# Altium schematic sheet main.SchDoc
size A4; SheetNumber: 2; SheetTotal: 5; SPICEModelCacheQOCYWOGJ: <root> / <DocumentId>QOCYWOGJ</DocumentId> / </root>
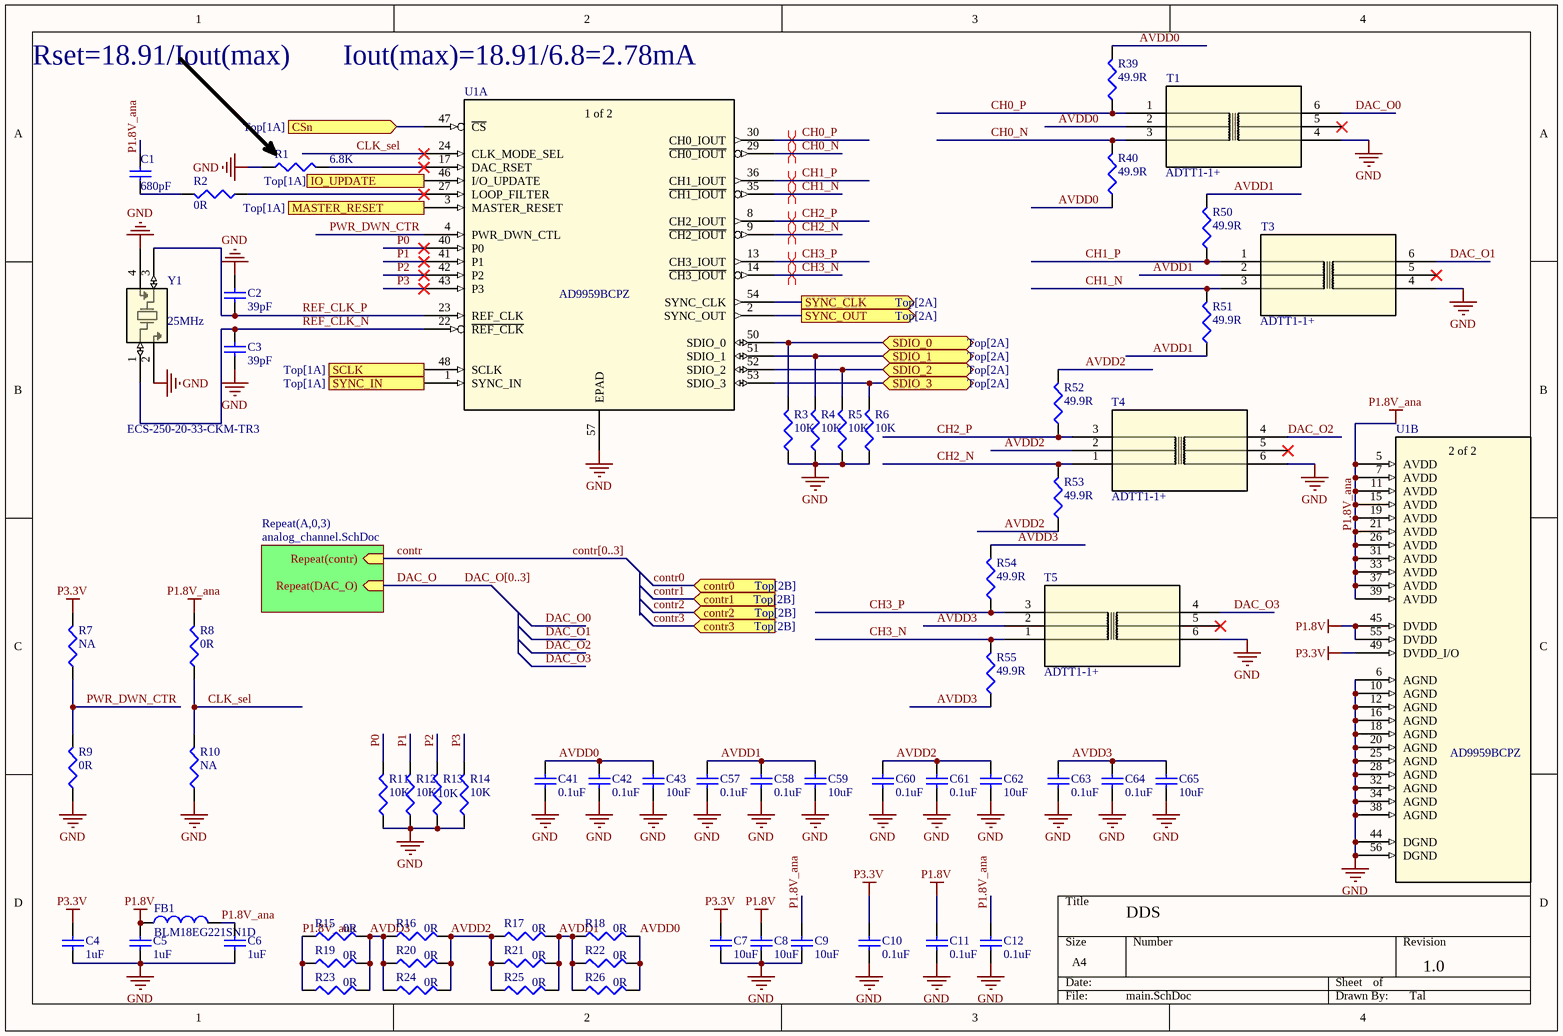
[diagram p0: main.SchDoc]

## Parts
C1  Capacitance: 680pF  [C0402]  (hidden comment: 680pF 50V)
C2  Capacitance: 39pF  [C0402]  (hidden comment: 39pF 50V)
C3  Capacitance: 39pF  [C0402]  (hidden comment: 39pF 50V)
C4  Capacitance: 1uF  [C0402]  (hidden comment: 1uF 25V)
C5  Capacitance: 1uF  [C0402]  (hidden comment: 1uF 25V)
C6  Capacitance: 1uF  [C0402]  (hidden comment: 1uF 25V)
C7  Capacitance: 10uF  [C0402]  (hidden comment: 10uF 10V)
C8  Capacitance: 10uF  [C0402]  (hidden comment: 10uF 10V)
C9  Capacitance: 10uF  [C0402]  (hidden comment: 10uF 10V)
C10  Capacitance: 0.1uF  [C0402]  (hidden comment: 0.1uF 50V)
C11  Capacitance: 0.1uF  [C0402]  (hidden comment: 0.1uF 50V)
C12  Capacitance: 0.1uF  [C0402]  (hidden comment: 0.1uF 50V)
C41  Capacitance: 0.1uF  [C0402]  (hidden comment: 0.1uF 50V)
C42  Capacitance: 0.1uF  [C0402]  (hidden comment: 0.1uF 50V)
C43  Capacitance: 10uF  [C0402]  (hidden comment: 10uF 10V)
C57  Capacitance: 0.1uF  [C0402]  (hidden comment: 0.1uF 50V)
C58  Capacitance: 0.1uF  [C0402]  (hidden comment: 0.1uF 50V)
C59  Capacitance: 10uF  [C0402]  (hidden comment: 10uF 10V)
C60  Capacitance: 0.1uF  [C0402]  (hidden comment: 0.1uF 50V)
C61  Capacitance: 0.1uF  [C0402]  (hidden comment: 0.1uF 50V)
C62  Capacitance: 10uF  [C0402]  (hidden comment: 10uF 10V)
C63  Capacitance: 0.1uF  [C0402]  (hidden comment: 0.1uF 50V)
C64  Capacitance: 0.1uF  [C0402]  (hidden comment: 0.1uF 50V)
C65  Capacitance: 10uF  [C0402]  (hidden comment: 10uF 10V)
FB1  BLM18EG221SN1D  [fb0603]
R1  6.8K  [R0402]
R2  0R  [R0402]
R3  10K  [R0402]
R4  10K  [R0402]
R5  10K  [R0402]
R6  10K  [R0402]
R7  NA  [R0402]
R8  0R  [R0402]
R9  0R  [R0402]
R10  NA  [R0402]
R11  10K  [R0402]
R12  10K  [R0402]
R13  10K  [R0402]
R14  10K  [R0402]
R15  0R  [R0805]
R16  0R  [R0805]
R17  0R  [R0805]
R18  0R  [R0805]
R19  0R  [R0805]
R20  0R  [R0805]
R21  0R  [R0805]
R22  0R  [R0805]
R23  0R  [R0805]
R24  0R  [R0805]
R25  0R  [R0805]
R26  0R  [R0805]
R39  49.9R  [R0402]
R40  49.9R  [R0402]
R50  49.9R  [R0402]
R51  49.9R  [R0402]
R52  49.9R  [R0402]
R53  49.9R  [R0402]
R54  49.9R  [R0402]
R55  49.9R  [R0402]
T1  ADTT1-1+  [CD542_MNC]
T3  ADTT1-1+  [CD542_MNC]
T4  ADTT1-1+  [CD542_MNC]
T5  ADTT1-1+  [CD542_MNC]
U1  AD9959BCPZ  [CP_56_1_ADI]  (parts A,B of 2)
Y1  ECS-250-20-33-CKM-TR3  [SMD4_ECX-32_3p2x2p5_ECS]

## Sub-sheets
Repeat(A,0,3) = analog_channel.SchDoc: Repeat(contr) (in), Repeat(DAC_O) (in)

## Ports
contr0 (in, see Top[2B]), contr1 (in, see Top[2B]), contr2 (in, see Top[2B]), contr3 (in, see Top[2B]), CSn (in, see Top[1A]), IO_UPDATE (in, see Top[1A]), MASTER_RESET (in, see Top[1A]), SCLK (in, see Top[1A]), SDIO_0 (bidir, see Top[2A]), SDIO_1 (bidir, see Top[2A]), SDIO_2 (bidir, see Top[2A]), SDIO_3 (bidir, see Top[2A]), SYNC_CLK (out, see Top[2A]), SYNC_IN (in, see Top[1A]), SYNC_OUT (out, see Top[2A])

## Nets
GND: C2.2 C3.1 C4.1 C5.1 C6.1 C7.1 C8.1 C9.1 C10.1 C11.1 C12.1 C41.1 C42.1 C43.1 C57.1 C58.1 C59.1 C60.1 C61.1 C62.1 C63.1 C64.1 C65.1 R1.1 R3.1 R4.1 R5.1 R6.1 R9.1 R10.1 R11.1 R12.1 R13.1 R14.1 T1.4 T3.4 T4.6 T5.6 U1.6(AGND) U1.10(AGND) U1.12(AGND) U1.16(AGND) U1.18(AGND) U1.20(AGND) U1.25(AGND) U1.28(AGND) U1.32(AGND) U1.34(AGND) U1.38(AGND) U1.44(DGND) U1.56(DGND) U1.57(EPAD) Y1.2 Y1.4
P1.8V: C5.2 C8.2 C11.2 FB1.1 U1.45(DVDD) U1.55(DVDD)
P1.8V_ana: C1.1 C6.2 C9.2 C12.2 FB1.2 R8.2 R15.1 R19.1 R23.1 U1.5(AVDD) U1.7(AVDD) U1.11(AVDD) U1.15(AVDD) U1.19(AVDD) U1.21(AVDD) U1.26(AVDD) U1.31(AVDD) U1.33(AVDD) U1.37(AVDD) U1.39(AVDD)
P3.3V: C4.2 C7.2 C10.2 R7.2 U1.49(DVDD_I/O)
AVDD0: C41.2 C42.2 C43.2 R18.2 R22.2 R26.2 R39.2 R40.1 T1.2
AVDD1: C57.2 C58.2 C59.2 R17.2 R18.1 R21.2 R22.1 R25.2 R26.1 R50.2 R51.1 T3.2
AVDD2: C60.2 C61.2 C62.2 R16.2 R17.1 R20.2 R21.1 R24.2 R25.1 R52.2 R53.1 T4.2
AVDD3: C63.2 C64.2 C65.2 R15.2 R16.1 R19.2 R20.1 R23.2 R24.1 R54.2 R55.1 T5.2
CH0_N: R40.2 T1.3 U1.29(~{CH0_IOUT})
CH0_P: R39.1 T1.1 U1.30(CH0_IOUT)
CH1_N: R51.2 T3.3 U1.35(~{CH1_IOUT})
CH1_P: R50.1 T3.1 U1.36(CH1_IOUT)
CH2_N: R53.2 T4.1 U1.9(~{CH2_IOUT})
CH2_P: R52.1 T4.3 U1.8(CH2_IOUT)
CH3_N: R55.2 T5.1 U1.14(~{CH3_IOUT})
CH3_P: R54.1 T5.3 U1.13(CH3_IOUT)
CLK_sel: R8.1 R10.2 U1.24(CLK_MODE_SEL)
CSn: U1.47(~{CS}) ; port CSn
DAC_O0: T1.6
DAC_O1: T3.6
DAC_O2: T4.4
DAC_O3: T5.4
IO_UPDATE: U1.46(I/O_UPDATE) ; port IO_UPDATE
MASTER_RESET: U1.3(MASTER_RESET) ; port MASTER_RESET
P0: R11.2 U1.40(P0)
P1: R12.2 U1.41(P1)
P2: R13.2 U1.42(P2)
P3: R14.2 U1.43(P3)
PWR_DWN_CTR: R7.1 R9.2 U1.4(PWR_DWN_CTL)
REF_CLK_N: C3.2 U1.22(~{REF_CLK}) Y1.1
REF_CLK_P: C2.1 U1.23(REF_CLK) Y1.3
SCLK: U1.48(SCLK) ; port SCLK
SDIO_0: R3.2 U1.50(SDIO_0) ; port SDIO_0
SDIO_1: R4.2 U1.51(SDIO_1) ; port SDIO_1
SDIO_2: R5.2 U1.52(SDIO_2) ; port SDIO_2
SDIO_3: R6.2 U1.53(SDIO_3) ; port SDIO_3
SYNC_CLK: U1.54(SYNC_CLK) ; port SYNC_CLK
SYNC_IN: U1.1(SYNC_IN) ; port SYNC_IN
SYNC_OUT: U1.2(SYNC_OUT) ; port SYNC_OUT
NetC1_2: C1.2 R2.2
NetR1_2: R1.2 U1.17(DAC_RSET)
NetR2_1: R2.1 U1.27(LOOP_FILTER)

Not connected (* = marked no-connect by the designer): T1 5*; T3 5*; T4 5*; T5 5*

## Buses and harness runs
bus contr[0..3]
bus DAC_O[0..3]

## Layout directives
differential pair: CH0_N, CH0_P, CH1_N, CH1_P, CH2_N, CH2_P, CH3_N, CH3_P

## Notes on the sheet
- Rset=18.91/Iout(max)
- Iout(max)=18.91/6.8=2.78mA
- (near Y1) 25MHz
- DDS
- 1.0
- Tal

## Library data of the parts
C1 = CAP CER 6.8pF 50V NP0 0402: CAP CER 680PF 50V NP0 0402; Manufacturer Part Number: C1005C0G1H6R8D; Manufacturer: TDK Corporation; LANDA P/N: ECP-000033
C2 C3 = CAP CER 6.8pF 50V NP0 0402: CAP CER 39PF 50V NP0 0402; Manufacturer Part Number: C1005C0G1H6R8D; Manufacturer: TDK Corporation; LANDA P/N: ECP-000033
C4-C6 = CAP CER 6.8pF 50V NP0 0402: CAP CER 1uF 25V X5R 0402; Manufacturer Part Number: C1005C0G1H6R8D; Manufacturer: TDK Corporation; LANDA P/N: ECP-000033; Voltage - Rated: 50V
C7-C9 C43 C59 C62 C65 = CAP CER 6.8pF 50V NP0 0402: CAP CER 10uF 10V X5R 0402; Manufacturer Part Number: C1005C0G1H6R8D; Manufacturer: TDK Corporation; LANDA P/N: ECP-000033; Voltage - Rated: 50V
C10-C12 C41 C42 C57 C58 C60 C61 C63 C64 = CAP CER 6.8pF 50V NP0 0402: CAP CER 0.1uF 50V NP0 0402; Manufacturer Part Number: C1005C0G1H6R8D; Manufacturer: TDK Corporation; LANDA P/N: ECP-000033
FB1 = BK1608HS600-T: FERRITE BEAD 220_OHM@100MHz 0603 2A 50mohm_DC; Manufacturer: Taiyo Yuden; LANDA P/N: EIN-000010
R1 = RES 3.09K OHM 1/16W 1% 0402: RES 6.8K OHM 1/16W 1% 0402; Manufacturer Part Number: RMCF0402FT3K09; Manufacturer: Stackpole Electronics Inc; Power (Watts): 0.063W, 1/16W; LANDA P/N: ERS-000063
R2 R7-R10 = RES 100 OHM 1/10W 1% 0402 SMD: RES 0 OHM 1/10W 1% 0402 SMD; Manufacturer Part Number: ERJ-2RKF1000X; Manufacturer: Panasonic Electronic Components; LANDA P/N: ERS-000079; Assembly: N.C
R3-R6 R11-R14 = RES 3.09K OHM 1/16W 1% 0402: RES 10K OHM 1/16W 1% 0402; Manufacturer Part Number: RMCF0402FT3K09; Manufacturer: Stackpole Electronics Inc; Power (Watts): 0.063W, 1/16W; LANDA P/N: ERS-000063
R15-R26 = RES 200 OHM 1/8W 1% 0805 SMD: RES 0 OHM 1/8W 1% 0805 SMD; Manufacturer Part Number: RMCF0805FT200R; Manufacturer: Stackpole Electronics Inc; Power (Watts): 0.125W, 1/8W; LANDA P/N: ERS-000050
R39 R40 R50-R55 = RES 100 OHM 1/10W 1% 0402 SMD: RES 49.9 OHM 1/10W 1% 0402 SMD; Manufacturer Part Number: ERJ-2RKF1000X; Manufacturer: Panasonic Electronic Components; LANDA P/N: ERS-000079; Assembly: N.C
T1 T3-T5 = ADTT1-1+: No Description Available; Mfr_Name: Mini Circuits; Type: DEV
U1 = AD9959BCPZ: No Description Available; Mfr_Name: Analog Devices Inc
Y1 = ECS-250-20-33-CKM-TR3: No Description Available; Mfr_Name: ECS International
